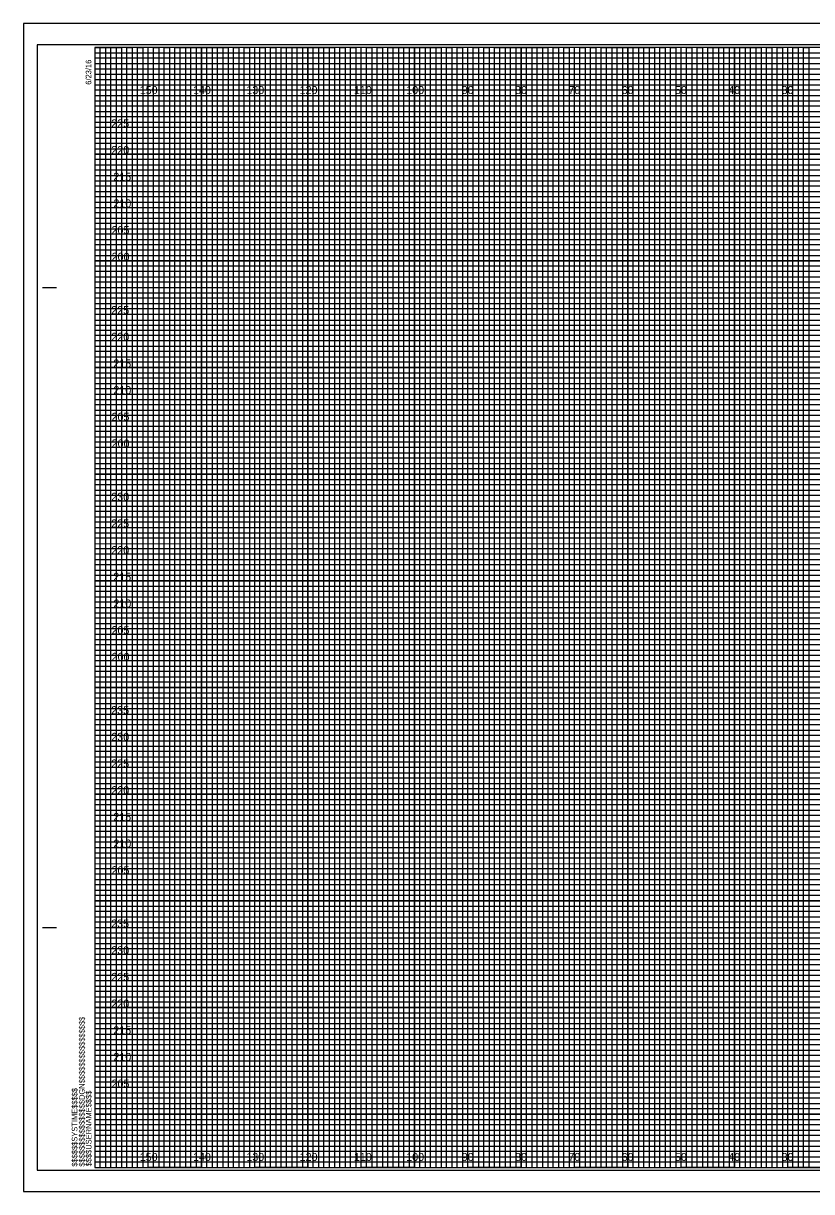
# Model space of a CAD drawing. Extents: x -13 to 323, y -5 to 434.
# Drawn here: x -13.4 to 134.5, y -4.5 to 214.5 of the extents above; entities that cross this region are included whole.
import ezdxf

# ---------------------------------------------------------------- set-up
doc = ezdxf.new("R2010")
doc.units = 0
for name, color, linetype in [('Prop XS Elevation Labels', 7, 'Continuous'), ('Prop XS Offset Labels', 7, 'Continuous'), ('Sheet Cross Section CELL', 7, 'Continuous'), ('Sheet Cross Section Grid Major CELL', 7, 'Continuous'), ('Sheet Cross Section Grid Middle CELL', 7, 'Continuous'), ('Sheet Cross Section Grid Minor 1 CELL', 7, 'Continuous'), ('Sheet Cross Section Grid Minor 2 CELL', 7, 'Continuous'), ('Sheet Cutting Line CELL', 7, 'Continuous'), ('Sheet DOT Grid CELL', 7, 'Continuous'), ('Sheet Plot Border Inside CELL', 7, 'Continuous'), ('Sheet Plot Border Outside CELL', 7, 'Continuous')]:
    doc.layers.add(name, color=color, linetype=linetype)

msp = doc.modelspace()

# ---------------------------------------------------------------- linework, layer by layer
at = {"layer": 'Sheet Cross Section CELL'}
for p, q in [((-9.8, 165), (-7.3, 165)), ((-9.7, 165), (-7.2, 165)), ((-9.8, 45), (-7.3, 45)), ((-9.7, 45), (-7.2, 45)), ((0, 0), (0, 0)), ((0, 0), (0, 0)), ((0, 0), (0, 0)), ((0, 0), (0, 0)), ((0, 0), (0, 0)), ((0, 0), (0, 0)), ((0, 0), (0, 0))]:
    msp.add_line(p, q, dxfattribs=at)
msp.add_lwpolyline([(320, 210), (0, 210), (0, 0), (320, 0)], close=True, dxfattribs=at)
at = {"layer": 'Sheet Cross Section Grid Major CELL'}
for p, q in [((10, 210), (0, 210)), ((10, 0), (10, 210)), ((30, 210), (20, 210)), ((20, 210), (20, 0)), ((30, 0), (30, 210)), ((50, 210), (40, 210)), ((40, 210), (40, 0)), ((50, 0), (50, 210)), ((70, 210), (60, 210)), ((60, 210), (60, 0)), ((70, 0), (70, 210)), ((90, 210), (80, 210)), ((80, 210), (80, 0)), ((90, 0), (90, 210)), ((110, 210), (100, 210)), ((100, 210), (100, 0)), ((110, 0), (110, 210)), ((130, 210), (120, 210)), ((120, 210), (120, 0)), ((130, 0), (130, 210)), ((20, 0), (10, 0)), ((40, 0), (30, 0)), ((60, 0), (50, 0)), ((80, 0), (70, 0)), ((100, 0), (90, 0)), ((120, 0), (110, 0)), ((140, 0), (130, 0))]:
    msp.add_line(p, q, dxfattribs=at)
for points in [[(0, 200), (320, 200), (320, 190), (0, 190)], [(0, 180), (320, 180), (320, 170), (0, 170)], [(0, 160), (320, 160), (320, 150), (0, 150)], [(0, 140), (320, 140), (320, 130), (0, 130)], [(0, 120), (320, 120), (320, 110), (0, 110)], [(0, 100), (320, 100), (320, 90), (0, 90)], [(0, 80), (320, 80), (320, 70), (0, 70)], [(0, 60), (320, 60), (320, 50), (0, 50)], [(0, 40), (320, 40), (320, 30), (0, 30)], [(0, 20), (320, 20), (320, 10), (0, 10)]]:
    msp.add_lwpolyline(points, dxfattribs=at)
at = {"layer": 'Sheet Cross Section Grid Middle CELL'}
for points in [[(0, 210), (5, 210), (5, 0), (15, 0), (15, 210), (25, 210), (25, 0), (35, 0), (35, 210), (45, 210), (45, 0), (55, 0), (55, 210), (65, 210), (65, 0), (75, 0), (75, 210), (85, 210), (85, 0), (95, 0), (95, 210), (105, 210), (105, 0), (115, 0), (115, 210), (125, 210), (125, 0), (135, 0)], [(0, 205), (275, 205)], [(0, 185), (320, 185), (320, 195), (0, 195)], [(0, 165), (320, 165), (320, 175), (0, 175)], [(0, 145), (320, 145), (320, 155), (0, 155)], [(0, 125), (320, 125), (320, 135), (0, 135)], [(0, 105), (320, 105), (320, 115), (0, 115)], [(0, 85), (320, 85), (320, 95), (0, 95)], [(0, 65), (320, 65), (320, 75), (0, 75)], [(0, 45), (320, 45), (320, 55), (0, 55)], [(0, 25), (320, 25), (320, 35), (0, 35)], [(0, 5), (320, 5), (320, 15), (0, 15)]]:
    msp.add_lwpolyline(points, dxfattribs=at)
at = {"layer": 'Sheet Cross Section Grid Minor 1 CELL'}
for p, q in [((0, 209), (260, 209)), ((260, 207.98), (0, 207.98)), ((0, 207.98), (0, 207)), ((0, 207), (260, 207)), ((260, 205.89), (0, 205.89)), ((0, 205.89), (0, 204)), ((0, 204), (320, 204))]:
    msp.add_line(p, q, dxfattribs=at)
for points in [[(0, 203), (270, 203), (320, 203), (320, 202), (0, 202)], [(0, 201), (320, 201), (320, 199), (0, 199)], [(0, 198), (320, 198), (320, 197), (0, 196.98)], [(0, 196), (320, 196), (320, 194), (0, 194)], [(0, 193), (320, 193), (320, 192), (0, 192)], [(0, 191), (320, 191), (320, 189), (0, 189)], [(0, 188), (320, 188), (320, 187), (0, 187)], [(0, 186), (320, 186), (320, 184), (0, 184)], [(0, 183), (320, 183), (320, 182), (0, 182)], [(0, 181), (320, 181), (320, 179), (0, 179)], [(0, 178), (320, 178), (320, 177), (0, 177)], [(0, 176), (320, 176), (320, 173.95), (320, 173), (320, 172), (0, 172)], [(0, 174), (320, 174), (320, 173), (0, 173)], [(0, 171), (320, 171), (320, 169), (0, 169.03)], [(0, 169.03), (320, 169), (320, 168), (0, 168)], [(0, 167), (320, 167), (320, 166), (0, 166)], [(0, 164), (320, 164), (320, 163), (0, 163)], [(0, 162), (320, 162), (320, 161), (0, 161)], [(-0.07, 158.89), (320, 158.89), (320, 157.88), (-0.07, 157.88)], [(0, 157), (320, 157), (320, 156), (0, 156)], [(0, 154), (320, 154), (320, 153), (0, 153)], [(0, 152), (320, 152), (320, 151), (0, 151)], [(0, 149), (320, 149), (320, 148), (0, 148)], [(0, 147), (320, 147), (320, 146), (0, 146)], [(0, 144), (320, 144), (320, 143), (0, 143)], [(0, 142), (320, 142), (320, 141), (0, 141)], [(0, 139), (320, 139), (319.99, 137.98), (0, 138)], [(0, 137), (320, 137), (320, 136), (0, 136)], [(0, 134), (320, 134), (320, 133), (0, 133)], [(0, 132), (320, 132), (320, 131), (0, 131)], [(0, 129), (320, 129), (320, 128), (0, 128)], [(0, 127), (320, 127), (320, 126), (0, 126)], [(0, 124), (320, 124), (320, 123), (0, 123)], [(0, 122), (320, 122), (320, 121), (0, 121)], [(0, 119), (320, 119), (320, 118), (0, 118)], [(0, 116.99), (320.07, 116.91), (320, 116), (0, 116)], [(0, 114), (320, 114), (320, 113), (0, 113)], [(0, 112), (320, 112), (320, 111), (0, 111)], [(0, 109), (320, 109), (320, 108), (0, 108)], [(0, 107), (320, 107), (320, 106), (0, 106)], [(0, 104), (320, 104), (320, 103), (0, 103)], [(0, 102), (320, 102), (320, 101), (0, 101)], [(0, 99), (320, 99), (320, 98), (0, 98)], [(0, 97), (320, 97), (320, 96), (0, 96)], [(0, 94), (320, 94), (320, 93), (0, 93)], [(0, 92), (320, 92), (320, 91), (0, 91)], [(0, 89), (320, 89), (320, 88), (0, 88)], [(0, 87), (320, 87), (320, 86), (0, 86)], [(0, 84), (320, 84), (320, 83), (0, 83)], [(0, 82), (320, 82), (320, 81), (0, 81)], [(0, 79), (320, 79), (319.99, 77.98), (0, 78)], [(0, 77), (320, 77), (320, 76), (0, 76)], [(0, 74), (320, 74), (320, 73), (0, 73)], [(0, 72), (320, 72), (320, 71), (0, 71)], [(0, 69), (320, 69), (320, 68), (0, 68)], [(0, 67), (320, 67), (320, 66), (0, 66)], [(0, 64), (320, 64), (320, 63), (0, 63)], [(0, 62), (320, 62), (320, 61), (0, 61)], [(0, 59), (320, 59), (320, 58), (0, 58)], [(0, 56.99), (320.07, 56.91), (320, 56), (0, 56)], [(0, 54), (320, 54), (320, 53), (0, 53)], [(0, 52), (320, 52), (320, 51), (0, 51)], [(0, 49), (320, 49), (320, 48), (0, 48)], [(0, 47), (320, 47), (320, 46), (0, 46)], [(0, 44), (320, 44), (320, 43), (0, 43)], [(0, 42), (320, 42), (320, 41), (0, 41)], [(0, 39), (320, 39), (320, 38), (0, 38)], [(0, 37), (320, 37), (320, 36), (0, 36)], [(0, 34), (320, 34), (320, 33), (0, 33)], [(0, 32), (320, 32), (320, 31), (0, 31)], [(0, 29), (320, 29), (320, 28), (0, 28)], [(0, 27), (320, 27), (320, 26), (0, 26)], [(0, 24), (320, 24), (320, 23), (0, 23)], [(0, 22), (320, 22), (320, 21), (0, 21)], [(0, 19), (320, 19), (320, 18), (0, 18)], [(0, 17), (320, 17), (320, 16), (0, 16)], [(0, 14), (320, 14), (320, 13), (0, 13)], [(0, 12), (320, 12), (320, 11), (0, 11)], [(0, 9), (320, 9), (320, 8), (0, 8)], [(0, 7), (320, 7), (320, 6), (0, 6)], [(0, 4), (320, 4), (320, 3), (0, 3)], [(0, 2), (320, 2), (320, 1), (0, 1)]]:
    msp.add_lwpolyline(points, dxfattribs=at)
at = {"layer": 'Sheet Cross Section Grid Minor 2 CELL'}
for points in [[(0, 0), (1, 0), (1, 210), (2, 210), (2, 0)], [(2, 0), (3, 0), (3, 210), (4, 210), (4, 0)], [(5, 0), (6, 0), (6, 210), (7, 210), (7, 0)], [(7, 0), (8, 0), (8, 210), (9, 210), (9, 0)], [(10, 0), (11, 0), (11, 210), (12, 210), (12, 0)], [(12, 0), (13, 0), (13, 210), (14, 210), (14, 0)], [(15, 0), (16, 0), (16, 210), (17, 210), (17, 0)], [(17, 0), (18, 0), (18, 210), (19, 210), (19, 0)], [(20, 0), (21, 0), (21, 210), (22, 210), (22, 0)], [(22, 0), (23, 0), (23, 210), (24, 210), (24, 0)], [(25, 0), (26, 0), (26, 210), (27, 210), (27, 0)], [(27, 0), (28, 0), (28, 210), (29, 210), (29, 0)], [(30, 0), (31, 0), (31, 210), (32, 210), (32, 0)], [(32, 0), (33, 0), (33, 210), (34, 210), (34, 0)], [(35, 0), (36, 0), (36, 210), (37, 210), (37, 0)], [(37, 0), (38, 0), (38, 210), (39, 210), (39, 0)], [(40, 0), (41, 0), (41, 210), (42, 210), (42, 0)], [(42, 0), (43, 0), (43, 210), (44, 210), (44, 0)], [(45, 0), (46, 0), (46, 210), (47, 210), (47, 0)], [(47, 0), (48, 0), (48, 210), (49, 210), (49, 0)], [(50, 0), (51, 0), (51, 210), (52, 210), (52, 0)], [(52, 0), (53, 0), (53, 210), (54, 210), (54, 0)], [(55, 0), (56, 0), (56, 210), (57, 210), (57, 0)], [(57, 0), (58, 0), (58, 210), (59, 210), (59, 0)], [(60, 0), (61, 0), (61, 210), (62, 210), (62, 0)], [(62, 0), (63, 0), (63, 210), (64, 210), (64, 0)], [(65, 0), (66, 0), (66, 210), (67, 210), (67, 0)], [(67, 0), (68, 0), (68, 210), (69, 210), (69, 0)], [(70, 0), (71, 0), (71, 210), (72, 210), (72, 0)], [(72, 0), (73, 0), (73, 210), (74, 210), (74, 0)], [(75, 0), (76, 0), (76, 210), (77, 210), (77, 0)], [(77, 0), (78, 0), (78, 210), (79, 210), (79, 0)], [(80, 0), (81, 0), (81, 210), (82, 210), (82, 0)], [(82, 0), (83, 0), (83, 210), (84, 210), (84, 0)], [(85, 0), (86, 0), (86, 210), (87, 210), (87, 0)], [(87, 0), (88, 0), (88, 210), (89, 210), (89, 0)], [(90, 0), (91, 0), (91, 210), (92, 210), (92, 0)], [(92, 0), (93, 0), (93, 210), (94, 210), (94, 0)], [(95, 0), (96, 0), (96, 210), (97, 210), (97, 0)], [(97, 0), (98, 0), (98, 210), (99, 210), (99, 0)], [(100, 0), (101, 0), (101, 210), (102, 210), (102, 0)], [(102, 0), (103, 0), (103, 210), (104, 210), (104, 0)], [(105, 0), (106, 0), (106, 210), (107, 210), (107, 0)], [(107, 0), (108, 0), (108, 210), (109, 210), (109, 0)], [(110, 0), (111, 0), (111, 210), (112, 210), (112, 0)], [(112, 0), (113, 0), (113, 210), (114, 210), (114, 0)], [(115, 0), (116, 0), (116, 210), (117, 210), (117, 0)], [(117, 0), (118, 0), (118, 210), (119, 210), (119, 0)], [(120, 0), (121, 0), (121, 210), (122, 210), (122, 0)], [(122, 0), (123, 0), (123, 210), (124, 210), (124, 0)], [(125, 0), (126, 0), (126, 210), (127, 210), (127, 0)], [(127, 0), (128, 0), (128, 210), (129, 210), (129, 0)], [(130, 0), (131, 0), (131, 210), (132, 210), (132, 0)], [(132, 0), (133, 0), (133, 210), (134, 210), (134, 0)]]:
    msp.add_lwpolyline(points, dxfattribs=at)
at = {"layer": 'Sheet Cutting Line CELL'}
for p, q in [((323.3, 214.5), (-13.4, 214.5)), ((-13.4, 214.5), (-13.4, -4.5)), ((-13.4, -4.5), (323.3, -4.5))]:
    msp.add_line(p, q, dxfattribs=at)
at = {"layer": 'Sheet DOT Grid CELL'}
for p, q in [((10, 0), (10, 210)), ((20, 0), (20, 210)), ((30, 0), (30, 210)), ((40, 0), (40, 210)), ((50, 0), (50, 210)), ((60, 0), (60, 210)), ((70, 0), (70, 210)), ((80, 0), (80, 210)), ((90, 0), (90, 210)), ((100, 0), (100, 210)), ((110, 0), (110, 210)), ((120, 0), (120, 210)), ((130, 0), (130, 210)), ((0, 200), (320, 200)), ((0, 190), (320, 190)), ((0, 180), (320, 180)), ((0, 170), (320, 170)), ((0, 160), (320, 160)), ((0, 150), (320, 150)), ((0, 140), (320, 140)), ((0, 130), (320, 130)), ((0, 120), (320, 120)), ((0, 110), (320, 110)), ((0, 100), (320, 100)), ((0, 90), (320, 90)), ((0, 80), (320, 80)), ((0, 70), (320, 70)), ((0, 60), (320, 60)), ((0, 50), (320, 50)), ((0, 40), (320, 40)), ((0, 30), (320, 30)), ((0, 20), (320, 20)), ((0, 10), (320, 10))]:
    msp.add_line(p, q, dxfattribs=at)
at = {"layer": 'Sheet Plot Border Inside CELL'}
msp.add_lwpolyline([(-10.8, -0.5), (322.4, -0.5), (322.4, 210.5), (-10.8, 210.5)], close=True, dxfattribs=at)
at = {"layer": 'Sheet Plot Border Outside CELL'}
msp.add_lwpolyline([(-13.4, -4.5), (323.3, -4.5), (323.3, 214.5), (-13.4, 214.5)], close=True, dxfattribs=at)

# ---------------------------------------------------------------- texts
at = {"layer": 'Prop XS Elevation Labels'}
for s, p in [('225', (3.1, 195)), ('220', (3.12, 190)), ('215', (3.48, 185)), ('210', (3.5, 180)), ('205', (3.15, 175)), ('200', (3.17, 170)), ('225', (3.1, 160)), ('220', (3.12, 155)), ('215', (3.48, 150)), ('210', (3.5, 145)), ('205', (3.15, 140)), ('200', (3.17, 135)), ('230', (3.11, 125)), ('225', (3.1, 120)), ('220', (3.12, 115)), ('215', (3.48, 110)), ('210', (3.5, 105)), ('205', (3.15, 100)), ('200', (3.17, 95)), ('235', (3.09, 85)), ('230', (3.11, 80)), ('225', (3.1, 75)), ('220', (3.12, 70)), ('215', (3.48, 65)), ('210', (3.5, 60)), ('205', (3.15, 55)), ('235', (3.09, 45)), ('230', (3.11, 40)), ('225', (3.1, 35)), ('220', (3.12, 30)), ('215', (3.48, 25)), ('210', (3.5, 20)), ('205', (3.15, 15))]:
    msp.add_text(s, height=1.5, dxfattribs=at).set_placement(p)
at = {"layer": 'Prop XS Offset Labels'}
for s, p in [('150', (8.44, 201.25)), ('140', (18.44, 201.25)), ('130', (28.44, 201.25)), ('120', (38.44, 201.25)), ('110', (48.62, 201.25)), ('100', (58.44, 201.25)), ('90', (68.86, 201.25)), ('80', (78.86, 201.25)), ('70', (88.86, 201.25)), ('60', (98.86, 201.25)), ('50', (108.86, 201.25)), ('40', (118.86, 201.25)), ('30', (128.86, 201.25)), ('150', (8.44, 1.25)), ('140', (18.44, 1.25)), ('130', (28.44, 1.25)), ('120', (38.44, 1.25)), ('110', (48.62, 1.25)), ('100', (58.44, 1.25)), ('90', (68.86, 1.25)), ('80', (78.86, 1.25)), ('70', (88.86, 1.25)), ('60', (98.86, 1.25)), ('50', (108.86, 1.25)), ('40', (118.86, 1.25)), ('30', (128.86, 1.25))]:
    msp.add_text(s, height=1.5, dxfattribs=at).set_placement(p)
at = {"layer": 'Sheet Cross Section CELL'}
for s, p in [('6/23/16', (-0.65, 203)), ('$$$$$$$$$$$$$$$$DGN$$$$$$$$$$$$$$$$', (-1.88, 0.18)), ('$$$$$$SYSTIME$$$$$', (-3.26, 0.18)), ('$$$$USERNAME$$$$', (-0.62, 0.23))]:
    msp.add_text(s, height=1.05, rotation=90, dxfattribs=at).set_placement(p)

doc.saveas('drawing.dxf')
